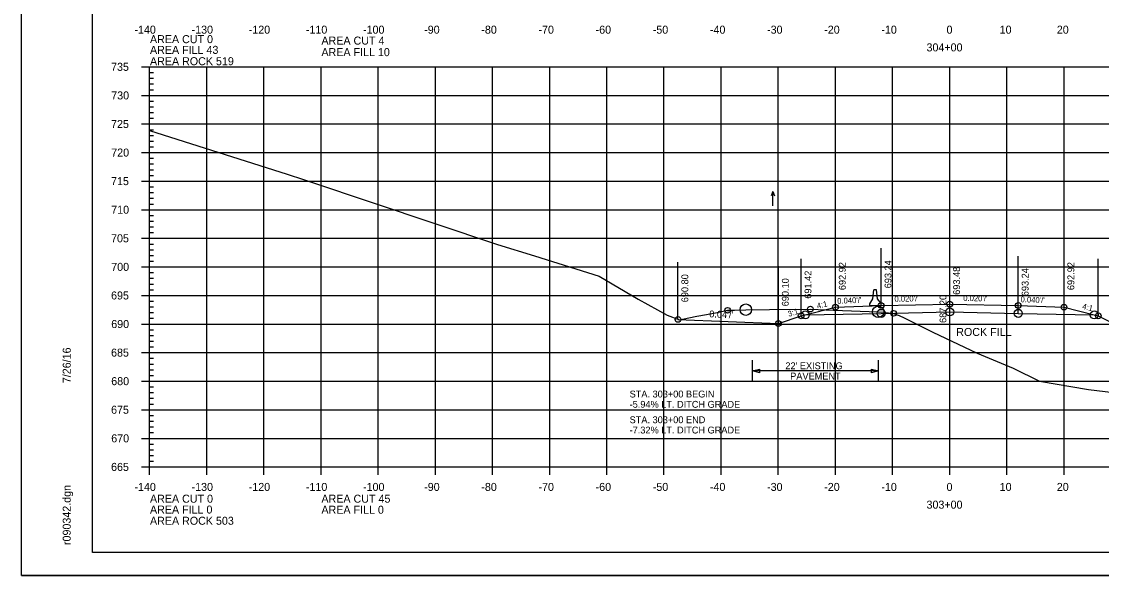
# Model space of a CAD drawing. Extents: x 1370515 to 1370849, y 383299 to 386073.
# Drawn here: x 1370515.4 to 1370704.3, y 383939.4 to 384036.3 of the extents above; entities that cross this region are included whole.
import ezdxf

# ---------------------------------------------------------------- set-up
doc = ezdxf.new("R2010")
doc.units = 0
for name, color, linetype in [('R_Alt Surface', 7, 'Continuous'), ('R_Axis', 7, 'Continuous'), ('R_Axis Annot', 7, 'Continuous'), ('R_Border', 7, 'Continuous'), ('R_Detour', 7, 'Continuous'), ('R_Drive', 7, 'Continuous'), ('R_Exist Surface', 7, 'Continuous'), ('R_Fin Surface', 7, 'Continuous'), ('R_Grid', 7, 'Continuous'), ('R_No Plot', 7, 'Continuous'), ('R_ROW Annot', 7, 'Continuous'), ('R_Water Annot', 7, 'Continuous'), ('R_Xsect Elev', 7, 'Continuous'), ('R_Xsect Slope', 7, 'Continuous')]:
    doc.layers.add(name, color=color, linetype=linetype)

msp = doc.modelspace()

# ---------------------------------------------------------------- linework, layer by layer
at = {"layer": 'R_Alt Surface'}
msp.add_lwpolyline([(1370652.52, 383985.02), (1370665.8, 383985.29), (1370677.8, 383985.53), (1370689.8, 383985.29), (1370703.09, 383985.02)], dxfattribs=at)
at = {"layer": 'R_Axis'}
for p, q in [((1370536.4, 384028.42), (1370539.2, 384028.42)), ((1370537.8, 383958.42), (1370537.8, 384028.42)), ((1370537.8, 384027.42), (1370538.5, 384027.42)), ((1370537.8, 384026.42), (1370538.5, 384026.42)), ((1370537.8, 384025.42), (1370538.5, 384025.42)), ((1370536.4, 384023.42), (1370539.2, 384023.42)), ((1370537.8, 384024.42), (1370538.5, 384024.42)), ((1370537.8, 384022.42), (1370538.5, 384022.42)), ((1370537.8, 384021.42), (1370538.5, 384021.42)), ((1370537.8, 384020.42), (1370538.5, 384020.42)), ((1370537.8, 384019.42), (1370538.5, 384019.42)), ((1370536.4, 384018.42), (1370539.2, 384018.42)), ((1370537.8, 384017.42), (1370538.5, 384017.42)), ((1370537.8, 384016.42), (1370538.5, 384016.42)), ((1370537.8, 384015.42), (1370538.5, 384015.42)), ((1370536.4, 384013.42), (1370539.2, 384013.42)), ((1370537.8, 384014.42), (1370538.5, 384014.42)), ((1370537.8, 384012.42), (1370538.5, 384012.42)), ((1370537.8, 384011.42), (1370538.5, 384011.42)), ((1370537.8, 384010.42), (1370538.5, 384010.42)), ((1370536.4, 384008.42), (1370539.2, 384008.42)), ((1370537.8, 384009.42), (1370538.5, 384009.42)), ((1370537.8, 384007.42), (1370538.5, 384007.42)), ((1370537.8, 384006.42), (1370538.5, 384006.42)), ((1370537.8, 384005.42), (1370538.5, 384005.42)), ((1370537.8, 384004.42), (1370538.5, 384004.42)), ((1370536.4, 384003.42), (1370539.2, 384003.42)), ((1370537.8, 384002.42), (1370538.5, 384002.42)), ((1370537.8, 384001.42), (1370538.5, 384001.42)), ((1370537.8, 384000.42), (1370538.5, 384000.42)), ((1370536.4, 383998.42), (1370539.2, 383998.42)), ((1370537.8, 383999.42), (1370538.5, 383999.42)), ((1370537.8, 383997.42), (1370538.5, 383997.42)), ((1370537.8, 383996.42), (1370538.5, 383996.42)), ((1370537.8, 383995.42), (1370538.5, 383995.42)), ((1370536.4, 383993.42), (1370539.2, 383993.42)), ((1370537.8, 383994.42), (1370538.5, 383994.42)), ((1370537.8, 383992.42), (1370538.5, 383992.42)), ((1370537.8, 383991.42), (1370538.5, 383991.42)), ((1370537.8, 383990.42), (1370538.5, 383990.42)), ((1370537.8, 383989.42), (1370538.5, 383989.42)), ((1370536.4, 383988.42), (1370539.2, 383988.42)), ((1370537.8, 383987.42), (1370538.5, 383987.42)), ((1370537.8, 383986.42), (1370538.5, 383986.42)), ((1370537.8, 383985.42), (1370538.5, 383985.42)), ((1370536.4, 383983.42), (1370539.2, 383983.42)), ((1370537.8, 383984.42), (1370538.5, 383984.42)), ((1370537.8, 383982.42), (1370538.5, 383982.42)), ((1370537.8, 383981.42), (1370538.5, 383981.42)), ((1370537.8, 383980.42), (1370538.5, 383980.42)), ((1370537.8, 383979.42), (1370538.5, 383979.42)), ((1370536.4, 383978.42), (1370539.2, 383978.42)), ((1370537.8, 383977.42), (1370538.5, 383977.42)), ((1370537.8, 383976.42), (1370538.5, 383976.42)), ((1370537.8, 383975.42), (1370538.5, 383975.42)), ((1370537.8, 383974.42), (1370538.5, 383974.42)), ((1370536.4, 383973.42), (1370539.2, 383973.42)), ((1370537.8, 383972.42), (1370538.5, 383972.42)), ((1370537.8, 383971.42), (1370538.5, 383971.42)), ((1370537.8, 383970.42), (1370538.5, 383970.42)), ((1370536.4, 383968.42), (1370539.2, 383968.42)), ((1370537.8, 383969.42), (1370538.5, 383969.42)), ((1370537.8, 383967.42), (1370538.5, 383967.42)), ((1370537.8, 383966.42), (1370538.5, 383966.42)), ((1370537.8, 383965.42), (1370538.5, 383965.42)), ((1370537.8, 383964.42), (1370538.5, 383964.42)), ((1370536.4, 383963.42), (1370539.2, 383963.42)), ((1370537.8, 383962.42), (1370538.5, 383962.42)), ((1370537.8, 383961.42), (1370538.5, 383961.42)), ((1370537.8, 383960.42), (1370538.5, 383960.42)), ((1370537.8, 383957.02), (1370537.8, 383959.82)), ((1370537.8, 383959.42), (1370538.5, 383959.42)), ((1370547.8, 383957.02), (1370547.8, 383959.82)), ((1370557.8, 383957.02), (1370557.8, 383959.82)), ((1370567.8, 383957.02), (1370567.8, 383959.82)), ((1370577.8, 383957.02), (1370577.8, 383959.82)), ((1370587.8, 383957.02), (1370587.8, 383959.82)), ((1370597.8, 383957.02), (1370597.8, 383959.82)), ((1370607.8, 383957.02), (1370607.8, 383959.82)), ((1370617.8, 383957.02), (1370617.8, 383959.82)), ((1370627.8, 383957.02), (1370627.8, 383959.82)), ((1370637.8, 383957.02), (1370637.8, 383959.82)), ((1370647.8, 383957.02), (1370647.8, 383959.82)), ((1370657.8, 383957.02), (1370657.8, 383959.82)), ((1370667.8, 383957.02), (1370667.8, 383959.82)), ((1370677.8, 383957.02), (1370677.8, 383959.82)), ((1370687.8, 383957.02), (1370687.8, 383959.82)), ((1370697.8, 383957.02), (1370697.8, 383959.82)), ((1370536.4, 383958.42), (1370539.2, 383958.42)), ((1370537.8, 383958.42), (1370817.8, 383958.42))]:
    msp.add_line(p, q, dxfattribs=at)
at = {"layer": 'R_Border'}
for p, q in [((1370527.8, 383943.42), (1370527.8, 384148.88)), ((1370527.8, 383943.42), (1370527.8, 383943.42)), ((1370843.98, 383943.42), (1370527.8, 383943.42))]:
    msp.add_line(p, q, dxfattribs=at)
at = {"layer": 'R_Detour'}
for p, q in [((1370664.36, 383987.8), (1370664.5, 383989.39)), ((1370664.75, 383989.39), (1370664.5, 383989.39)), ((1370665, 383989.4), (1370664.75, 383989.39)), ((1370665.19, 383987.82), (1370665, 383989.4)), ((1370663.8, 383986.96), (1370664.36, 383987.8)), ((1370663.8, 383986.63), (1370663.8, 383986.96)), ((1370665.8, 383987), (1370665.19, 383987.82)), ((1370665.8, 383986.67), (1370665.8, 383987)), ((1370665.8, 383986.67), (1370663.8, 383986.63))]:
    msp.add_line(p, q, dxfattribs=at)
at = {"layer": 'R_Exist Surface'}
msp.add_lwpolyline([(1370537.8, 384017.27), (1370561.84, 384009.62), (1370564.74, 384008.69), (1370565.79, 384008.33), (1370598.65, 383997.34), (1370605.12, 383995.37), (1370616.47, 383991.82), (1370623.26, 383987.79), (1370628.37, 383984.95), (1370630.49, 383984.13), (1370632.17, 383984.49), (1370633.54, 383984.77), (1370635.23, 383985.06), (1370636.8, 383985.35), (1370637.64, 383985.53), (1370638.94, 383985.82), (1370640.15, 383985.86), (1370642.12, 383985.93), (1370646.25, 383985.98), (1370653.41, 383986.04), (1370657.46, 383985.87), (1370665.29, 383985.55), (1370666.19, 383985.47), (1370667.99, 383985.29), (1370668.98, 383984.89), (1370669.81, 383984.5), (1370674.84, 383982.02), (1370682.61, 383978.35), (1370688.91, 383975.68), (1370693.5, 383973.44), (1370702.07, 383971.95), (1370713.31, 383970.65)], dxfattribs=at)
at = {"layer": 'R_Fin Surface'}
msp.add_lwpolyline([(1370630.25, 383984.23), (1370647.83, 383983.52), (1370651.8, 383984.85), (1370652.52, 383985.02), (1370657.8, 383986.35), (1370665.8, 383986.67), (1370677.8, 383986.91), (1370689.8, 383986.67), (1370697.8, 383986.35), (1370703.09, 383985.02), (1370703.8, 383984.85), (1370730.65, 383971.42), (1370737.96, 383971.42)], dxfattribs=at)
at = {"layer": 'R_Grid'}
for p, q in [((1370537.8, 384028.42), (1370817.8, 384028.42)), ((1370537.8, 383958.42), (1370537.8, 384028.42)), ((1370547.8, 383958.42), (1370547.8, 384028.42)), ((1370557.8, 383958.42), (1370557.8, 384028.42)), ((1370567.8, 383958.42), (1370567.8, 384028.42)), ((1370577.8, 383958.42), (1370577.8, 384028.42)), ((1370587.8, 383958.42), (1370587.8, 384028.42)), ((1370597.8, 383958.42), (1370597.8, 384028.42)), ((1370607.8, 383958.42), (1370607.8, 384028.42)), ((1370617.8, 383958.42), (1370617.8, 384028.42)), ((1370627.8, 383958.42), (1370627.8, 384028.42)), ((1370637.8, 383958.42), (1370637.8, 384028.42)), ((1370647.8, 383958.42), (1370647.8, 384028.42)), ((1370657.8, 383958.42), (1370657.8, 384028.42)), ((1370667.8, 383958.42), (1370667.8, 384028.42)), ((1370677.8, 383958.42), (1370677.8, 384028.42)), ((1370687.8, 383958.42), (1370687.8, 384028.42)), ((1370697.8, 383958.42), (1370697.8, 384028.42)), ((1370537.8, 384023.42), (1370817.8, 384023.42)), ((1370537.8, 384018.42), (1370817.8, 384018.42)), ((1370537.8, 384013.42), (1370817.8, 384013.42)), ((1370537.8, 384008.42), (1370817.8, 384008.42)), ((1370537.8, 384003.42), (1370817.8, 384003.42)), ((1370537.8, 383998.42), (1370817.8, 383998.42)), ((1370537.8, 383993.42), (1370817.8, 383993.42)), ((1370537.8, 383988.42), (1370817.8, 383988.42)), ((1370537.8, 383983.42), (1370817.8, 383983.42)), ((1370537.8, 383978.42), (1370817.8, 383978.42)), ((1370537.8, 383973.42), (1370817.8, 383973.42)), ((1370537.8, 383968.42), (1370817.8, 383968.42)), ((1370537.8, 383963.42), (1370817.8, 383963.42)), ((1370537.8, 383958.42), (1370817.8, 383958.42))]:
    msp.add_line(p, q, dxfattribs=at)
at = {"layer": 'R_No Plot'}
msp.add_line((1370515.4, 383939.44), (1370848.73, 383939.44), dxfattribs=at)
for points in [[(1370515.39, 384152.78), (1370848.73, 384152.78), (1370848.73, 383939.44), (1370515.39, 383939.44)], [(1370761.72, 384148.88), (1370761.72, 384139), (1370797.45, 384139), (1370797.45, 384136.08), (1370820.65, 384136.08), (1370820.65, 384112.87), (1370843.98, 384112.87), (1370843.98, 383943.42), (1370527.8, 383943.42), (1370527.8, 384148.88)]]:
    msp.add_lwpolyline(points, close=True, dxfattribs=at)
for centre, radius in [((1370642.12, 383985.93), 1), ((1370665.8, 383986.67), 0.5), ((1370677.8, 383986.91), 0.5), ((1370689.8, 383986.67), 0.5), ((1370638.94, 383985.82), 0.5), ((1370651.8, 383984.85), 0.5), ((1370651.8, 383984.85), 0.5), ((1370652.52, 383985.02), 0.7), ((1370653.41, 383986.04), 0.5), ((1370657.8, 383986.35), 0.5), ((1370665.29, 383985.55), 1), ((1370665.8, 383985.29), 0.7), ((1370667.99, 383985.29), 0.5), ((1370677.8, 383985.53), 0.7), ((1370677.8, 383985.53), 0.7), ((1370689.8, 383985.29), 0.7), ((1370697.8, 383986.35), 0.5), ((1370703.09, 383985.02), 0.7), ((1370703.8, 383984.85), 0.5), ((1370703.8, 383984.85), 0.5), ((1370630.25, 383984.23), 0.5), ((1370647.83, 383983.52), 0.5)]:
    msp.add_circle(centre, radius, dxfattribs=at)
at = {"layer": 'R_ROW Annot'}
for p, q in [((1370643.31, 383973.33), (1370643.31, 383977.09)), ((1370665.31, 383973.33), (1370665.31, 383977.09)), ((1370665.31, 383975.21), (1370643.31, 383975.21))]:
    msp.add_line(p, q, dxfattribs=at)
for points in [[(1370644.51, 383974.91), (1370643.31, 383975.21), (1370644.51, 383975.51)], [(1370664.11, 383975.51), (1370665.31, 383975.21), (1370664.11, 383974.91)]]:
    msp.add_lwpolyline(points, close=True, dxfattribs=at)
at = {"layer": 'R_Water Annot'}
for p, q in [((1370646.86, 384006.59), (1370646.58, 384005.82)), ((1370646.86, 384004.08), (1370646.86, 384006.59)), ((1370646.86, 384006.59), (1370647.14, 384005.82))]:
    msp.add_line(p, q, dxfattribs=at)
at = {"layer": 'R_Xsect Elev'}
for p, q in [((1370665.8, 383986.67), (1370665.8, 383996.67)), ((1370651.8, 383984.85), (1370651.8, 383994.85)), ((1370657.8, 383986.35), (1370657.8, 383996.35)), ((1370677.8, 383985.53), (1370677.8, 383995.53)), ((1370689.8, 383985.29), (1370689.8, 383995.29)), ((1370697.8, 383986.35), (1370697.8, 383996.35)), ((1370703.8, 383984.85), (1370703.8, 383994.85)), ((1370630.25, 383984.23), (1370630.25, 383994.23)), ((1370647.83, 383983.52), (1370647.83, 383993.52)), ((1370677.82, 383980.61), (1370677.82, 383990.61))]:
    msp.add_line(p, q, dxfattribs=at)

# ---------------------------------------------------------------- texts
at = {"layer": 'R_Axis'}
msp.add_text('-', height=0.0001, dxfattribs=at).set_placement((1370537.8, 383958.42))
at = {"layer": 'R_Axis Annot'}
for s, p in [('-140', (1370535.14, 384034.22)), ('-130', (1370545.14, 384034.22)), ('-120', (1370555.14, 384034.22)), ('-110', (1370565.14, 384034.22)), ('-100', (1370575.14, 384034.22)), ('-90', (1370585.84, 384034.22)), ('-80', (1370595.84, 384034.22)), ('-70', (1370605.84, 384034.22)), ('-60', (1370615.84, 384034.22)), ('-50', (1370625.84, 384034.22)), ('-40', (1370635.84, 384034.22)), ('-30', (1370645.84, 384034.22)), ('-20', (1370655.84, 384034.22)), ('-10', (1370665.84, 384034.22)), ('0', (1370677.24, 384034.22)), ('10', (1370686.54, 384034.22)), ('20', (1370696.54, 384034.22)), ('AREA CUT 0', (1370537.86, 384032.56)), ('AREA CUT 4', (1370567.86, 384032.31)), ('304+00', (1370673.74, 384031.12)), ('AREA FILL 43', (1370537.86, 384030.69)), ('AREA FILL 10', (1370567.86, 384030.29)), ('735', (1370531.05, 384027.72)), ('AREA ROCK 519', (1370537.86, 384028.7)), ('730', (1370531.08, 384022.72)), ('725', (1370531.05, 384017.72)), ('720', (1370531.08, 384012.72)), ('715', (1370531.05, 384007.72)), ('710', (1370531.08, 384002.72)), ('705', (1370531.05, 383997.72)), ('700', (1370531.08, 383992.72)), ('695', (1370531.05, 383987.72)), ('690', (1370531.08, 383982.72)), ('ROCK FILL', (1370678.94, 383981.33)), ('685', (1370531.05, 383977.72)), ('680', (1370531.08, 383972.72)), ('675', (1370531.05, 383967.72)), ('670', (1370531.08, 383962.72)), ('665', (1370531.05, 383957.72)), ('-140', (1370535.14, 383954.22)), ('-130', (1370545.14, 383954.22)), ('-120', (1370555.14, 383954.22)), ('-110', (1370565.14, 383954.22)), ('-100', (1370575.14, 383954.22)), ('-90', (1370585.84, 383954.22)), ('-80', (1370595.84, 383954.22)), ('-70', (1370605.84, 383954.22)), ('-60', (1370615.84, 383954.22)), ('-50', (1370625.84, 383954.22)), ('-40', (1370635.84, 383954.22)), ('-30', (1370645.84, 383954.22)), ('-20', (1370655.84, 383954.22)), ('-10', (1370665.84, 383954.22)), ('0', (1370677.24, 383954.22)), ('10', (1370686.54, 383954.22)), ('20', (1370696.54, 383954.22)), ('AREA CUT 0', (1370537.86, 383952.16)), ('AREA CUT 45', (1370567.86, 383952.16)), ('AREA FILL 0', (1370537.86, 383950.26)), ('AREA FILL 0', (1370567.86, 383950.23)), ('303+00', (1370673.74, 383951.12)), ('AREA ROCK 503', (1370537.86, 383948.3))]:
    msp.add_text(s, height=1.4, dxfattribs=at).set_placement(p)
at = {"layer": 'R_Border'}
for s, p in [('7/26/16', (1370523.99, 383973.07)), ('r090342.dgn', (1370523.99, 383944.75))]:
    msp.add_text(s, height=1.4, rotation=90, dxfattribs=at).set_placement(p)
at = {"layer": 'R_Detour'}
msp.add_text("0.04'/'", height=1.2, rotation=357.7094, dxfattribs=at).set_placement((1370635.71, 383984.6))
at = {"layer": 'R_Drive'}
for s, p in [('STA. 303+00 BEGIN', (1370621.79, 383970.57)), ('-5.94% LT. DITCH GRADE', (1370621.79, 383968.77)), ('STA. 303+00 END', (1370621.79, 383966.07)), ('-7.32% LT. DITCH GRADE', (1370621.79, 383964.27))]:
    msp.add_text(s, height=1.2, dxfattribs=at).set_placement(p)
at = {"layer": 'R_No Plot'}
for p in [(1370564.69, 384008.64), (1370598.61, 383997.29), (1370616.42, 383991.77), (1370636.76, 383985.3), (1370630.45, 383984.08), (1370633.5, 383984.72), (1370669.77, 383984.45), (1370682.56, 383978.3), (1370693.45, 383973.39)]:
    msp.add_text('+', height=0.1, dxfattribs=at).set_placement(p)
at = {"layer": 'R_ROW Annot'}
for s, p in [("22' EXISTING", (1370649.04, 383975.51)), ('PAVEMENT', (1370649.89, 383973.71))]:
    msp.add_text(s, height=1.2, dxfattribs=at).set_placement(p)
at = {"layer": 'R_Xsect Elev'}
for s, p in [('693.24', (1370667.6, 383989.67)), ('691.42', (1370653.6, 383987.85)), ('692.92', (1370659.6, 383989.35)), ('693.48', (1370679.6, 383988.53)), ('693.24', (1370691.6, 383988.29)), ('692.92', (1370699.6, 383989.35)), ('690.80', (1370632.05, 383987.23)), ('690.10', (1370649.63, 383986.52)), ('687.20', (1370677.22, 383983.61))]:
    msp.add_text(s, height=1.2, rotation=90, dxfattribs=at).set_placement(p)
at = {"layer": 'R_Xsect Slope'}
for s, rotation, p in [('4:1', 14.0362, (1370654.68, 383986.08)), ("0.040'/'", 2.2906, (1370658.13, 383986.96)), ("0.020'/'", 1.1458, (1370668.14, 383987.31)), ("0.020'/'", 358.8542, (1370680.16, 383987.46)), ("0.040'/'", 357.7094, (1370690.18, 383987.25)), ('4:1', 345.9638, (1370700.92, 383986.08)), ('3:1', 18.4349, (1370649.66, 383984.66))]:
    msp.add_text(s, height=1, rotation=rotation, dxfattribs=at).set_placement(p)

doc.saveas('drawing.dxf')
